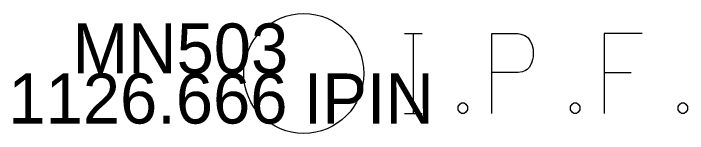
# Model space of a CAD drawing. Extents: x 2402028 to 2407435, y 498611 to 499105.
# Drawn here: x 2404196.6 to 2404210.07, y 498894.16 to 498896.56 of the extents above; entities that cross this region are included whole.
import ezdxf

# ---------------------------------------------------------------- set-up
doc = ezdxf.new("R2010")
doc.units = 0
for name, color, linetype in [('_CIVIL_CONSTRUCTION', 7, 'Continuous'), ('RW_X_CL_100_Bearings', 7, 'Continuous'), ('RW_X_CL_100_Cardinal_Points', 7, 'Continuous'), ('RW_X_CL_100_Stations', 7, 'Continuous')]:
    doc.layers.add(name, color=color, linetype=linetype)

msp = doc.modelspace()

# ---------------------------------------------------------------- linework, layer by layer
at = {"layer": 'RW_X_CL_100_Stations'}
for points in [[(2404204.416, 498896.159), (2404204.769, 498896.159)], [(2404204.592, 498894.559), (2404204.592, 498896.159)], [(2404206.158, 498894.559), (2404206.158, 498896.159), (2404206.687, 498896.159), (2404206.742, 498896.146), (2404206.819, 498896.121), (2404206.852, 498896.096), (2404206.885, 498896.071), (2404206.929, 498896.008), (2404206.962, 498895.945), (2404206.984, 498895.844), (2404206.984, 498895.693), (2404206.973, 498895.642), (2404206.951, 498895.567), (2404206.907, 498895.479), (2404206.863, 498895.441), (2404206.83, 498895.416), (2404206.775, 498895.39), (2404206.687, 498895.378), (2404206.158, 498895.378)], [(2404209.167, 498896.159), (2404208.406, 498896.159), (2404208.406, 498894.559)], [(2404208.406, 498895.378), (2404208.946, 498895.378)], [(2404205.551, 498894.773), (2404205.606, 498894.773), (2404205.64, 498894.748), (2404205.672, 498894.698), (2404205.672, 498894.635), (2404205.64, 498894.584), (2404205.606, 498894.559), (2404205.551, 498894.559), (2404205.518, 498894.584), (2404205.485, 498894.635), (2404205.485, 498894.698), (2404205.518, 498894.748), (2404205.551, 498894.773)], [(2404207.8, 498894.773), (2404207.855, 498894.773), (2404207.888, 498894.748), (2404207.921, 498894.698), (2404207.921, 498894.635), (2404207.888, 498894.584), (2404207.855, 498894.559), (2404207.8, 498894.559), (2404207.767, 498894.584), (2404207.734, 498894.635), (2404207.734, 498894.698), (2404207.767, 498894.748), (2404207.8, 498894.773)], [(2404209.949, 498894.773), (2404210.004, 498894.773), (2404210.038, 498894.748), (2404210.071, 498894.698), (2404210.071, 498894.635), (2404210.038, 498894.584), (2404210.004, 498894.559), (2404209.949, 498894.559), (2404209.916, 498894.584), (2404209.883, 498894.635), (2404209.883, 498894.698), (2404209.916, 498894.748), (2404209.949, 498894.773)], [(2404204.416, 498894.559), (2404204.769, 498894.559)]]:
    msp.add_lwpolyline(points, dxfattribs=at)
msp.add_circle((2404202.401, 498895.359), 1.2, dxfattribs=at)

# ---------------------------------------------------------------- texts
at = {"layer": '_CIVIL_CONSTRUCTION'}
msp.add_text('MN503', height=1, dxfattribs=at).set_placement((2404197.781, 498895.359))
at = {"layer": 'RW_X_CL_100_Bearings'}
msp.add_text('1126.666', height=1, dxfattribs=at).set_placement((2404196.499, 498894.359))
at = {"layer": 'RW_X_CL_100_Cardinal_Points'}
msp.add_text('IPIN', height=1, dxfattribs=at).set_placement((2404202.401, 498894.359))

doc.saveas('drawing.dxf')
